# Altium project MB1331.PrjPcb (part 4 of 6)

## Sheet MFX.SchDoc: MFX I/O Expander
size A4; Date: Not used; ApprovedBy: Not used; CheckedBy: Not used; Author: Not used; CompanyName: STMicroelectronics; DrawnBy: Not used; Engineer: Not used; Organization: Not used; Address1: Not used; Address2: Not used; Address3: Not used; Address4: Not used; DocumentNumber: Not used; Revision: Not used; SheetNumber: 18; SheetTotal: 23
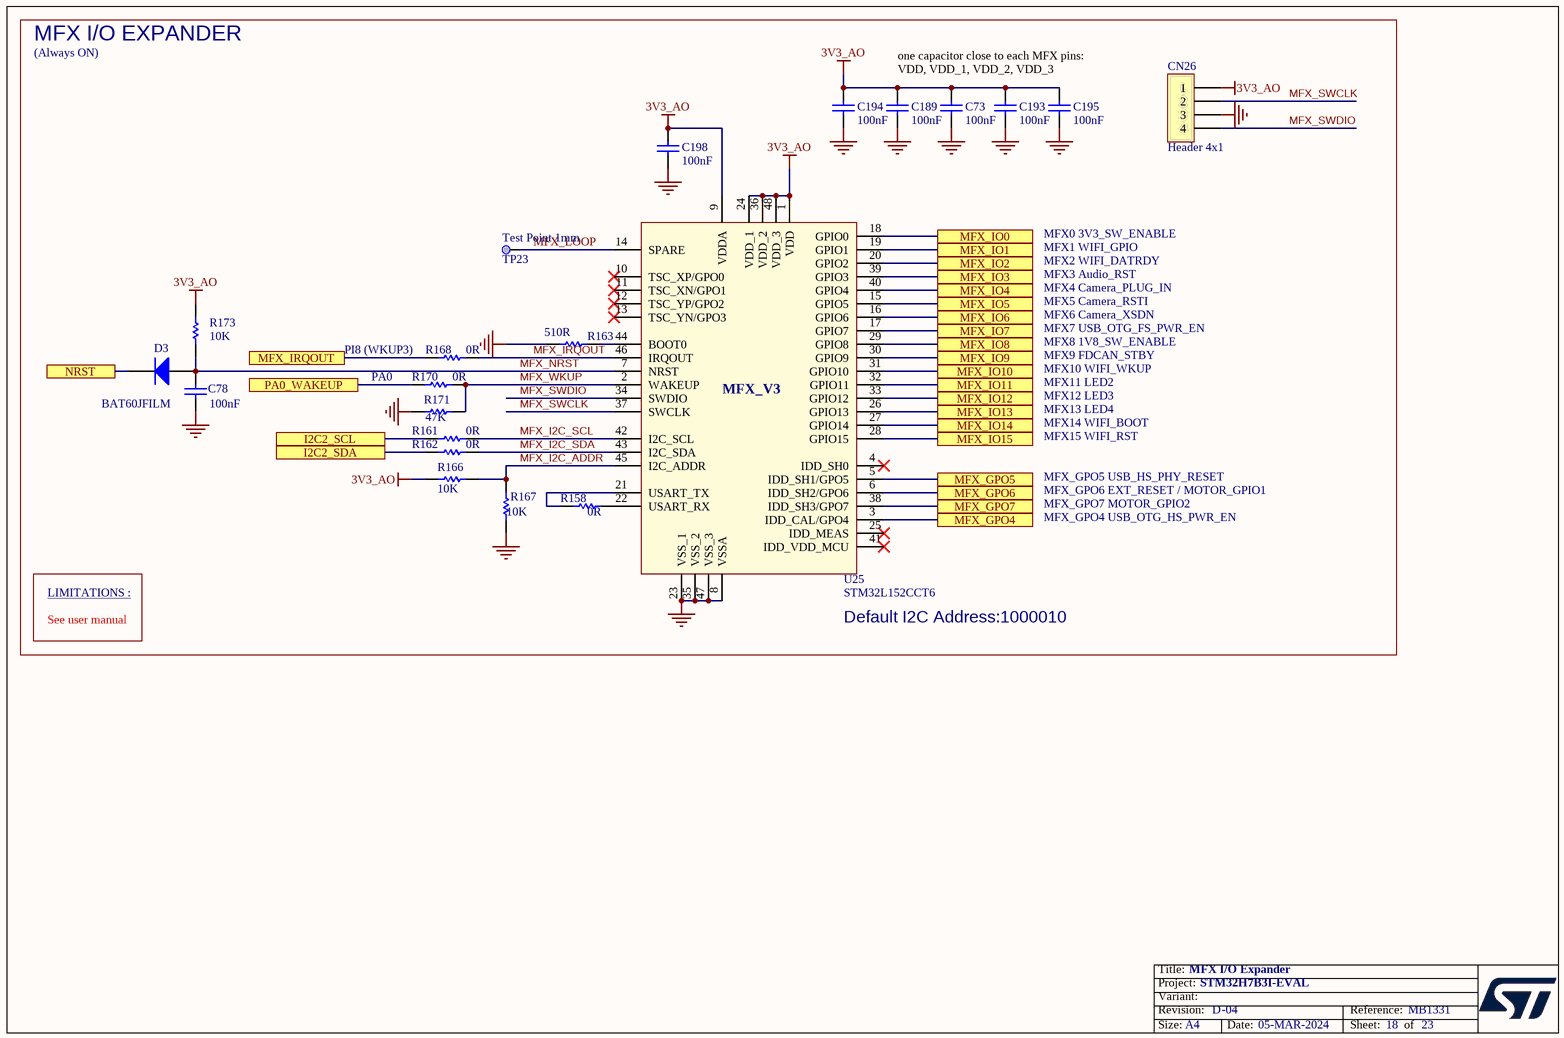
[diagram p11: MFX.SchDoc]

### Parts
C73  value 100nF  [C0402]  (hidden comment: Capacitor)
C78  value 100nF  [C0402]  (hidden comment: Capacitor)
C189  value 100nF  [C0402]  (hidden comment: Capacitor)
C193  value 100nF  [C0402]  (hidden comment: Capacitor)
C194  value 100nF  [C0402]  (hidden comment: Capacitor)
C195  value 100nF  [C0402]  (hidden comment: Capacitor)
C198  value 100nF  [C0402]  (hidden comment: Capacitor)
CN26  Header 4x1  [CON_SAMTEC_TSW-104-07-G-S]
D3  BAT60JFILM  [DIO_SOD323]
R158  value 0R  [R0603]  (hidden comment: Resistor)
R161  value 0R  [R0402]  (hidden comment: Resistor)
R162  value 0R  [R0402]  (hidden comment: Resistor)
R163  value 510R  [R0402]  (hidden comment: Resistor)
R166  value 10K  [R0402]  (hidden comment: Resistor)
R167  value 10K  [R0402]  (hidden comment: Resistor)
R168  value 0R  [R0603]  (hidden comment: Resistor)
R170  value 0R  [R0603]  (hidden comment: Resistor)
R171  value 47K  [R0402]  (hidden comment: Resistor)
R173  value 10K  [R0402]  (hidden comment: Resistor)
TP23  value Test Point 1mm  [TP_SMD_1MM]  (hidden comment: Test Point)  (no BOM)
U25  STM32L152CCT6  [ICC_LQFP48_7X7_P050]

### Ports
I2C2_SCL, I2C2_SDA, MFX_GPO4, MFX_GPO5, MFX_GPO6, MFX_GPO7, MFX_IO0, MFX_IO1, MFX_IO2, MFX_IO3, MFX_IO4, MFX_IO5, MFX_IO6, MFX_IO7, MFX_IO8, MFX_IO9, MFX_IO10, MFX_IO11, MFX_IO12, MFX_IO13, MFX_IO14, MFX_IO15, MFX_IRQOUT, NRST, PA0_WAKEUP

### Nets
3V3_AO: C73.1 C189.2 C193.2 C194.2 C195.2 C198.2 CN26.1 R166.1 R173.2 U25.1(VDD) U25.9(VDDA) U25.24(VDD_1) U25.36(VDD_2) U25.48(VDD_3)
GND: C73.2 C78.1 C189.1 C193.1 C194.1 C195.1 C198.1 CN26.3 R163.2 R167.2 R171.1 U25.8(VSSA) U25.23(VSS_1) U25.35(VSS_2) U25.47(VSS_3)
I2C2_SCL: R161.1 ; port I2C2_SCL
I2C2_SDA: R162.1 ; port I2C2_SDA
MFX_GPO4: U25.3(IDD_CAL/GPO4) ; port MFX_GPO4
MFX_GPO5: U25.5(IDD_SH1/GPO5) ; port MFX_GPO5
MFX_GPO6: U25.6(IDD_SH2/GPO6) ; port MFX_GPO6
MFX_GPO7: U25.38(IDD_SH3/GPO7) ; port MFX_GPO7
MFX_I2C_ADDR: R166.2 R167.1 U25.45(I2C_ADDR)
MFX_I2C_SCL: R161.2 U25.42(I2C_SCL)
MFX_I2C_SDA: R162.2 U25.43(I2C_SDA)
MFX_IO0: U25.18(GPIO0) ; port MFX_IO0
MFX_IO1: U25.19(GPIO1) ; port MFX_IO1
MFX_IO2: U25.20(GPIO2) ; port MFX_IO2
MFX_IO3: U25.39(GPIO3) ; port MFX_IO3
MFX_IO4: U25.40(GPIO4) ; port MFX_IO4
MFX_IO5: U25.15(GPIO5) ; port MFX_IO5
MFX_IO6: U25.16(GPIO6) ; port MFX_IO6
MFX_IO7: U25.17(GPIO7) ; port MFX_IO7
MFX_IO8: U25.29(GPIO8) ; port MFX_IO8
MFX_IO9: U25.30(GPIO9) ; port MFX_IO9
MFX_IO10: U25.31(GPIO10) ; port MFX_IO10
MFX_IO11: U25.32(GPIO11) ; port MFX_IO11
MFX_IO12: U25.33(GPIO12) ; port MFX_IO12
MFX_IO13: U25.26(GPIO13) ; port MFX_IO13
MFX_IO14: U25.27(GPIO14) ; port MFX_IO14
MFX_IO15: U25.28(GPIO15) ; port MFX_IO15
MFX_IRQOUT: R168.2 U25.46(IRQOUT)
MFX_LOOP: TP23.1 U25.14(SPARE)
MFX_NRST: C78.2 D3.1(A) R173.1 U25.7(NRST)
MFX_SWCLK: CN26.2 U25.37(SWCLK)
MFX_SWDIO: CN26.4 U25.34(SWDIO)
MFX_WKUP: R170.1 R171.2 U25.2(WAKEUP)
NRST: D3.2(K) ; port NRST
PA0_WAKEUP: R170.2 ; port PA0_WAKEUP
PI8: R168.1 ; port MFX_IRQOUT
NetR158_1: R158.1 U25.21(USART_TX)
NetR158_2: R158.2 U25.22(USART_RX)
NetR163_1: R163.1 U25.44(BOOT0)

Not connected (* = marked no-connect by the designer): U25 4(IDD_SH0)* 10(TSC_XP/GPO0)* 11(TSC_XN/GPO1)* 12(TSC_YP/GPO2)* 13(TSC_YN/GPO3)* 25(IDD_MEAS)* 41(IDD_VDD_MCU)*

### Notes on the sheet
- MFX I/O EXPANDER
- (Always ON)
- one capacitor close to each MFX pins: VDD, VDD_1, VDD_2, VDD_3
- PI8 (WKUP3)
- PA0
- MFX0	3V3_SW_ENABLE
  MFX1	WIFI_GPIO
  MFX2	WIFI_DATRDY
  MFX3	Audio_RST
  MFX4	Camera_PLUG_IN
  MFX5	Camera_RSTI
  MFX6	Camera_XSDN
  MFX7	USB_OTG_FS_PWR_EN
  MFX8	1V8_SW_ENABLE
  MFX9	FDCAN_STBY
  MFX10	WIFI_WKUP
  MFX11	LED2
  MFX12	LED3
  MFX13	LED4
  MFX14	WIFI_BOOT
  MFX15	WIFI_RST
- MFX_GPO5	USB_HS_PHY_RESET
  MFX_GPO6	EXT_RESET / MOTOR_GPIO1
  MFX_GPO7	MOTOR_GPIO2
  MFX_GPO4	USB_OTG_HS_PWR_EN
- LIMITATIONS :
- See user manual
- (near U25) Default I2C Address:1000010

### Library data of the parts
C73 C78 C189 C193-C195 C198 = MCD-00006: Capacitor, MLCC, 100nF, 16V, X7R, 10%, 0402, T=0.5mm; Manufacturer_Part_Number: CC0402KRX7R7BB104; Manufacturer: YAGEO; Alternate_Manufacturer_Part_Number: GCM155R71C104KA55D; Alternate_Manufacturer: MURATA; Part_Preference: Recommended; Partial_Alternate_Internal_Part_Number: MCD-03299; Provided_By: SUBCO; ECCN_US: EAR99; ECCN_EU: NEC; Component_Country_Of_Origin: China; ID: 2474; Order_Code_RS: 9402047; ShowFields: YES
CN26 = MCD-00029: Header, 4x1, 2,54mm, VR, TH, Height 5.84mm/2.54mm; Manufacturer_Part_Number: TSW-104-07-G-S; Manufacturer: SAMTEC; Part_Type: Connector; Part_Preference: Recommended; Provided_By: SUBCO; Component_Country_Of_Origin: China, Costa Rica, Malaysia, USA, Vietnam; ID: 2487; Order_Code_RS: 2667450; ShowFields: YES
D3 = MCD-00034: Manufacturer: STMICROELECTRONICS; Part_Type: Diode; BMS_Part_Number: 9151097; Manufacturer_HQ_COO: EU; Part_Preference: Recommended; Provided_By: SUBCO with ST control; ECCN_US: EAR99; ECCN_EU: NEC; Component_Country_Of_Origin: China; ID: 2483; Order_Code_RS: 714-6879; ShowFields: YES
R158 R168 R170 = MCD-00056: Resistor,0R,0603,5%,1/10W; Manufacturer_Part_Number: RC0603JR-070RL; Manufacturer: YAGEO; Part_Preference: Recommended; Provided_By: SUBCO; ECCN_US: EAR99; ECCN_EU: NEC; Component_Country_Of_Origin: China; ID: 2536; Order_Code_RS: 9233130RL; ShowFields: YES
R161 R162 = MCD-00052: Resistor,0R,0402,5%,1/16W; Manufacturer_Part_Number: RC0402JR-070RL; Manufacturer: YAGEO; Part_Preference: Recommended; Provided_By: SUBCO; ECCN_US: EAR99; ECCN_EU: NEC; Component_Country_Of_Origin: China; ID: 2540; Order_Code_RS: 9232516RL; ShowFields: YES
R163 = MCD-00064: Resistor,510R,0402,1%,1/16W; Manufacturer_Part_Number: RC0402FR-07510RL; Manufacturer: YAGEO; Part_Preference: Recommended; Provided_By: SUBCO; ECCN_US: EAR99; ECCN_EU: NEC; Component_Country_Of_Origin: China; ID: 2525; Order_Code_RS: 1458804; ShowFields: YES
R166 R167 R173 = MCD-00053: Resistor,10K,0402,1%,1/16W; Manufacturer_Part_Number: RC0402FR-0710KL; Manufacturer: YAGEO; BMS_Part_Number: 9131590; Part_Preference: Recommended; Provided_By: SUBCO; ECCN_US: EAR99; ECCN_EU: NEC; Component_Country_Of_Origin: China; ID: 2539; Order_Code_RS: 9239359; ShowFields: YES
R171 = MCD-00063: Resistor,47K,0402,1%,1/16W; Manufacturer_Part_Number: RC0402FR-0747KL; Manufacturer: YAGEO; Part_Preference: Recommended; Provided_By: SUBCO; ECCN_US: EAR99; ECCN_EU: NEC; Component_Country_Of_Origin: China; ID: 2528; Order_Code_RS: 9239430; ShowFields: YES
TP23 = MCD-00074: Test Point 1mm; Part_Type: Misc; Part_Preference: Recommended; Component_Country_Of_Origin: Unknown; ID: 2518; ShowFields: YES
U25 = MCD-00135: Ultra-low-power 32-bit MCU ARM; Manufacturer: STMICROELECTRONICS; Part_Type: IC; BMS_Part_Number: 9175875; Manufacturer_HQ_COO: EU; Part_Preference: Forbidden; Provided_By: SUBCO with ST control; ECCN_US: 3A991A2; ECCN_EU: NEC; Component_Country_Of_Origin: China; ID: 2734; Order_Code_RS: 110-7090; ShowFields: YES

## Sheet MotorControl.SchDoc: Motor Control
size A4; SheetNumber: 17; SheetTotal: 23
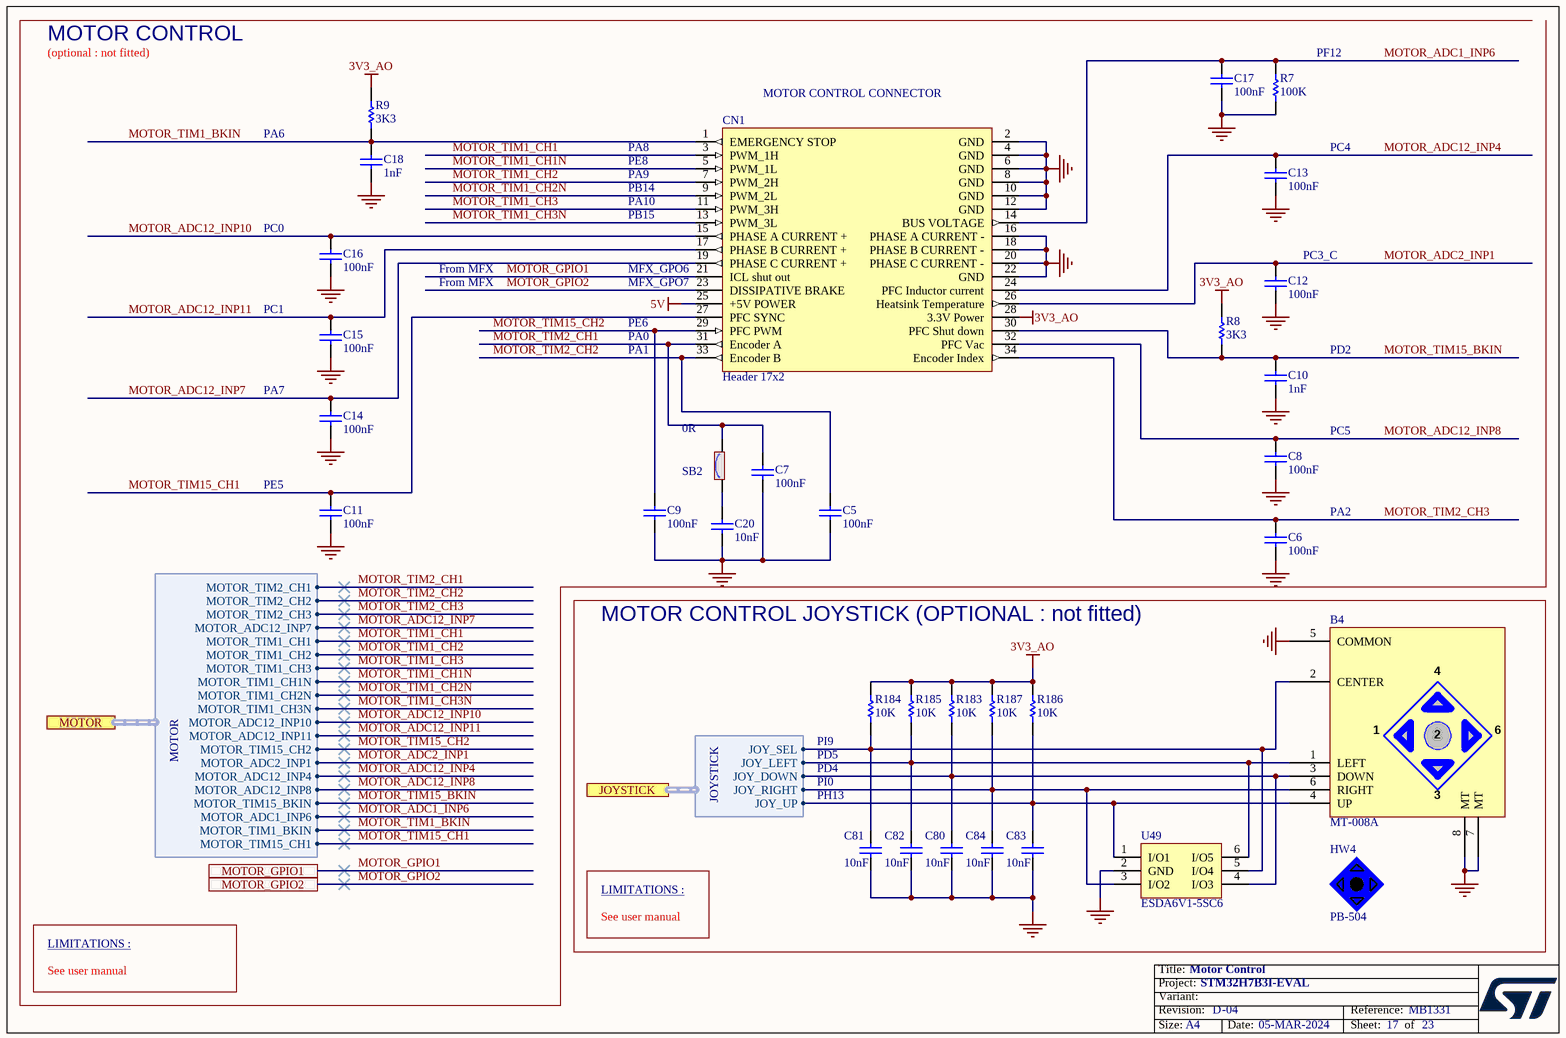
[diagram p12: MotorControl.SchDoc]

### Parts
B4  value MT-008A  [SWI_XIEJIA_MT-008A_6P]  (hidden comment: Joystick MT-008A_M)
C5  value 100nF  [C0402]  (hidden comment: Capacitor)
C6  value 100nF  [C0402]  (hidden comment: Capacitor)
C7  value 100nF  [C0402]  (hidden comment: Capacitor)
C8  value 100nF  [C0402]  (hidden comment: Capacitor)
C9  value 100nF  [C0402]  (hidden comment: Capacitor)
C10  value 1nF  [C0402]  (hidden comment: Capacitor)
C11  value 100nF  [C0402]  (hidden comment: Capacitor)
C12  value 100nF  [C0402]  (hidden comment: Capacitor)
C13  value 100nF  [C0402]  (hidden comment: Capacitor)
C14  value 100nF  [C0402]  (hidden comment: Capacitor)
C15  value 100nF  [C0402]  (hidden comment: Capacitor)
C16  value 100nF  [C0402]  (hidden comment: Capacitor)
C17  value 100nF  [C0402]  (hidden comment: Capacitor)
C18  value 1nF  [C0402]  (hidden comment: Capacitor)
C20  value 10nF  [C0402]  (hidden comment: Capacitor)
C80  value 10nF  [C0402]  (hidden comment: Capacitor)
C81  value 10nF  [C0402]  (hidden comment: Capacitor)
C82  value 10nF  [C0402]  (hidden comment: Capacitor)
C83  value 10nF  [C0402]  (hidden comment: Capacitor)
C84  value 10nF  [C0402]  (hidden comment: Capacitor)
CN1  value Header 17x2  [CON_SAMTEC_TST-117-01-T-D]  (hidden comment: Header 17x2 IDC34 MotorControl)
HW4  value PB-504  (hidden comment: JOYSTICK_BLUE_HAT)  (mechanical)
R7  value 100K  [R0603]  (hidden comment: Resistor)
R8  value 3K3  [R0402]  (hidden comment: Resistor)
R9  value 3K3  [R0402]  (hidden comment: Resistor)
R183  value 10K  [R0402]  (hidden comment: Resistor)
R184  value 10K  [R0402]  (hidden comment: Resistor)
R185  value 10K  [R0402]  (hidden comment: Resistor)
R186  value 10K  [R0402]  (hidden comment: Resistor)
R187  value 10K  [R0402]  (hidden comment: Resistor)
SB2  value 0R  [SOLDER-BRIDGE_R0603-0R]  (hidden comment: SB_ON)
U49  ESDA6V1-5SC6  [ESD_SOT23-6L]

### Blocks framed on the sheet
MOTOR CONTROL JOYSTICK (OPTIONAL : not fitted): B4 C80-C84 HW4 R183-R187 U49

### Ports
JOYSTICK (harness JOYSTICK), MOTOR (harness MOTOR), MOTOR_GPIO1, MOTOR_GPIO2

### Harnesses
MOTOR: MOTOR_TIM2_CH1, MOTOR_TIM2_CH2, MOTOR_TIM2_CH3, MOTOR_ADC12_INP7, MOTOR_TIM1_CH1, MOTOR_TIM1_CH2, MOTOR_TIM1_CH3, MOTOR_TIM1_CH1N, MOTOR_TIM1_CH2N, MOTOR_TIM1_CH3N, MOTOR_ADC12_INP10, MOTOR_ADC12_INP11, MOTOR_TIM15_CH2, MOTOR_ADC2_INP1, MOTOR_ADC12_INP4, MOTOR_ADC12_INP8, MOTOR_TIM15_BKIN, MOTOR_ADC1_INP6, MOTOR_TIM1_BKIN, MOTOR_TIM15_CH1
JOYSTICK: JOY_SEL, JOY_LEFT, JOY_DOWN, JOY_RIGHT, JOY_UP

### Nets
3V3_AO: CN1.28(3.3V_Power) R8.2 R9.2 R183.2 R184.2 R185.2 R186.2 R187.2
5V: CN1.25(+5V_POWER)
GND: B4.5(COMMON) B4.7(MT) B4.8(MT) C5.1 C6.1 C7.1 C8.1 C9.1 C10.1 C11.1 C12.1 C13.1 C14.1 C15.1 C16.1 C17.1 C18.1 C20.1 C80.1 C81.1 C82.1 C83.1 C84.1 CN1.2(GND) CN1.4(GND) CN1.6(GND) CN1.8(GND) CN1.10(GND) CN1.12(GND) CN1.16(PHASE_A_CURRENT_-) CN1.18(PHASE_B_CURRENT_-) CN1.20(PHASE_C_CURRENT_-) CN1.22(GND) R7.1 U49.2(GND)
MOTOR_ADC1_INP6: C17.2 CN1.14(BUS_VOLTAGE) R7.2 ; port MOTOR.MOTOR_ADC1_INP6
MOTOR_ADC2_INP1: C12.2 CN1.26(Heatsink_Temperature) ; port MOTOR.MOTOR_ADC2_INP1
MOTOR_ADC12_INP4: C13.2 CN1.24(PFC_Inductor_current) ; port MOTOR.MOTOR_ADC12_INP4
MOTOR_ADC12_INP7: C14.2 CN1.19(PHASE_C_CURRENT_+) ; port MOTOR.MOTOR_ADC12_INP7
MOTOR_ADC12_INP8: C8.2 CN1.32(PFC_Vac) ; port MOTOR.MOTOR_ADC12_INP8
MOTOR_ADC12_INP10: C16.2 CN1.15(PHASE_A_CURRENT_+) ; port MOTOR.MOTOR_ADC12_INP10
MOTOR_ADC12_INP11: C15.2 CN1.17(PHASE_B_CURRENT_+) ; port MOTOR.MOTOR_ADC12_INP11
MOTOR_GPIO1: CN1.21(ICL_shut_out) ; port MOTOR_GPIO1
MOTOR_GPIO2: CN1.23(DISSIPATIVE_BRAKE) ; port MOTOR_GPIO2
MOTOR_TIM1_BKIN: C18.2 CN1.1(EMERGENCY_STOP) R9.1 ; port MOTOR.MOTOR_TIM1_BKIN
MOTOR_TIM1_CH1: CN1.3(PWM_1H) ; port MOTOR.MOTOR_TIM1_CH1
MOTOR_TIM1_CH1N: CN1.5(PWM_1L) ; port MOTOR.MOTOR_TIM1_CH1N
MOTOR_TIM1_CH2: CN1.7(PWM_2H) ; port MOTOR.MOTOR_TIM1_CH2
MOTOR_TIM1_CH2N: CN1.9(PWM_2L) ; port MOTOR.MOTOR_TIM1_CH2N
MOTOR_TIM1_CH3: CN1.11(PWM_3H) ; port MOTOR.MOTOR_TIM1_CH3
MOTOR_TIM1_CH3N: CN1.13(PWM_3L) ; port MOTOR.MOTOR_TIM1_CH3N
MOTOR_TIM2_CH1: C7.2 CN1.31(Encoder_A) SB2.1 ; port MOTOR.MOTOR_TIM2_CH1
MOTOR_TIM2_CH2: C5.2 CN1.33(Encoder_B) ; port MOTOR.MOTOR_TIM2_CH2
MOTOR_TIM2_CH3: C6.2 CN1.34(Encoder_Index) ; port MOTOR.MOTOR_TIM2_CH3
MOTOR_TIM15_BKIN: C10.2 CN1.30(PFC_Shut_down) R8.1 ; port MOTOR.MOTOR_TIM15_BKIN
MOTOR_TIM15_CH1: C11.2 CN1.27(PFC_SYNC) ; port MOTOR.MOTOR_TIM15_CH1
MOTOR_TIM15_CH2: C9.2 CN1.29(PFC_PWM) ; port MOTOR.MOTOR_TIM15_CH2
NetB4_1: B4.1(LEFT) C82.2 R185.1 U49.6(I/O5) ; port JOYSTICK.JOY_LEFT
NetB4_2: B4.2(CENTER) C81.2 R184.1 U49.5(I/O4) ; port JOYSTICK.JOY_SEL
NetB4_3: B4.3(DOWN) C80.2 R183.1 U49.4(I/O3) ; port JOYSTICK.JOY_DOWN
NetB4_4: B4.4(UP) C83.2 R186.1 U49.1(I/O1) ; port JOYSTICK.JOY_UP
NetB4_6: B4.6(RIGHT) C84.2 R187.1 U49.3(I/O2) ; port JOYSTICK.JOY_RIGHT
NetC20_2: C20.2 SB2.2

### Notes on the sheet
- MOTOR CONTROL
- (optional : not fitted)
- (near CN1) MOTOR CONTROL CONNECTOR
- (near R7) PF12
- PA6
- PA9
- PA8
- PE8
- PC4
- (near C16) PC0
- PB14
- PB15
- PA10
- PC1
- From MFX
- (near CN1) MFX_GPO6
- (near CN1) MFX_GPO7
- (near C12) PC3_C
- PA1
- PA0
- PE6
- PD2
- PA7
- PC5
- PE5
- PA2
- (near R184) PD5
- PD4
- PI0
- (near R184) PI9
- PH13
- LIMITATIONS :
- See user manual

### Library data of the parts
B4 = MCD-00132: Joystick, 4 dir, 1 OK; Part_Type: Misc; Manufacturer: XIEJIA Electronics; BMS_Part_Number: 9180124; Part_Preference: Recommended; Provided_By: SUBCO; Component_Country_Of_Origin: Unknown; ID: 2736; ShowFields: YES
C5-C9 C11-C17 = MCD-00006: as C73 on sheet MFX
C10 C18 = MCD-00198: Capacitor, MLCC, 1nF, 16V, X7R, 10%, 0402, T=0.5mm; Manufacturer_Part_Number: CC0402KRX7R7BB102; Manufacturer: YAGEO; Part_Preference: Recommended; Provided_By: SUBCO; ECCN_US: EAR99; ECCN_EU: NEC; Component_Country_Of_Origin: China; ID: 2665; ShowFields: YES
C20 C80-C84 = MCD-00011: Capacitor, MLCC, 10nF, 16V, X7R, 10%, 0402, T=0.5mm; Manufacturer_Part_Number: CC0402KRX7R7BB103; Manufacturer: YAGEO; Part_Preference: Recommended; Provided_By: SUBCO; ECCN_US: EAR99; ECCN_EU: NEC; Component_Country_Of_Origin: China; ID: 2469; Order_Code_RS: 3019275; ShowFields: YES
CN1 = MCD-00583: Header, 17x2, 2.54mm, VR, TH, Height 8.89mm/2.92mm, shrouded; Manufacturer_Part_Number: TST-117-01-T-D; Manufacturer: SAMTEC; Part_Type: Connector; Alternate_Manufacturer_Part_Number: BHFS03-34G01BT1; Alternate_Manufacturer: WINPIN; Part_Preference: Recommended; Provided_By: SUBCO; Component_Country_Of_Origin: China, Costa Rica, Malaysia, USA, Vietnam; ID: 3161; ShowFields: YES
HW4 = MCD-01337: Joystick Blue Hat; Part_Type: Misc; Manufacturer: JIUBABA; Part_Preference: Alternate; Provided_By: SUBCO; Alternate_EMS: A; Component_Country_Of_Origin: Unknown; ID: 3437; ShowFields: YES
R7 = MCD-00223: Resistor,100K,0603,1%,1/10W; Manufacturer_Part_Number: RC0603FR-07100KL; Manufacturer: YAGEO; Part_Preference: Recommended; Provided_By: SUBCO; ECCN_US: EAR99; ECCN_EU: NEC; Component_Country_Of_Origin: China; ID: 2647; ShowFields: YES
R8 R9 = MCD-00184: Resistor,3K3,0402,1%,1/16W; Manufacturer_Part_Number: RC0402FR-073K3L; Manufacturer: YAGEO; BMS_Part_Number: 9131946; Part_Preference: Recommended; Provided_By: SUBCO; ECCN_US: EAR99; ECCN_EU: NEC; Component_Country_Of_Origin: China; ID: 2684; ShowFields: YES
R183-R187 = MCD-00053: as R166 on sheet MFX
SB2 = MCD-00071: Solder Bridge ON; Part_Type: Resistor; Manufacturer_Part_Number: RC0603JR-070RL; Manufacturer: YAGEO; Manufacturer_HQ_COO: Unknown; Part_Preference: Recommended; Provided_By: SUBCO; Component_Country_Of_Origin: China; ID: 2521; Order_Code_RS: 199-5647; ShowFields: YES
U49 = MCD-01066: 5 unidirectional Transil diodes ESD protection; Part_Type: Diode; Manufacturer: STMICROELECTRONICS; BMS_Part_Number: 9179044; Manufacturer_HQ_COO: EU; Part_Preference: Recommended; Provided_By: SUBCO with ST control; ECCN_US: EAR99; ECCN_EU: NEC; Component_Country_Of_Origin: China; ID: 3425; Order_Code_RS: 250-066; ShowFields: YES

## Sheet OCSPI.SchDoc: OCSPI
size A4; Date: Not used; ApprovedBy: Not used; CheckedBy: Not used; Author: Not used; CompanyName: STMicroelectronics; DrawnBy: Not used; Engineer: Not used; Organization: Not used; Address1: Not used; Address2: Not used; Address3: Not used; Address4: Not used; DocumentNumber: Not used; Revision: Not used; SheetNumber: 8; SheetTotal: 23
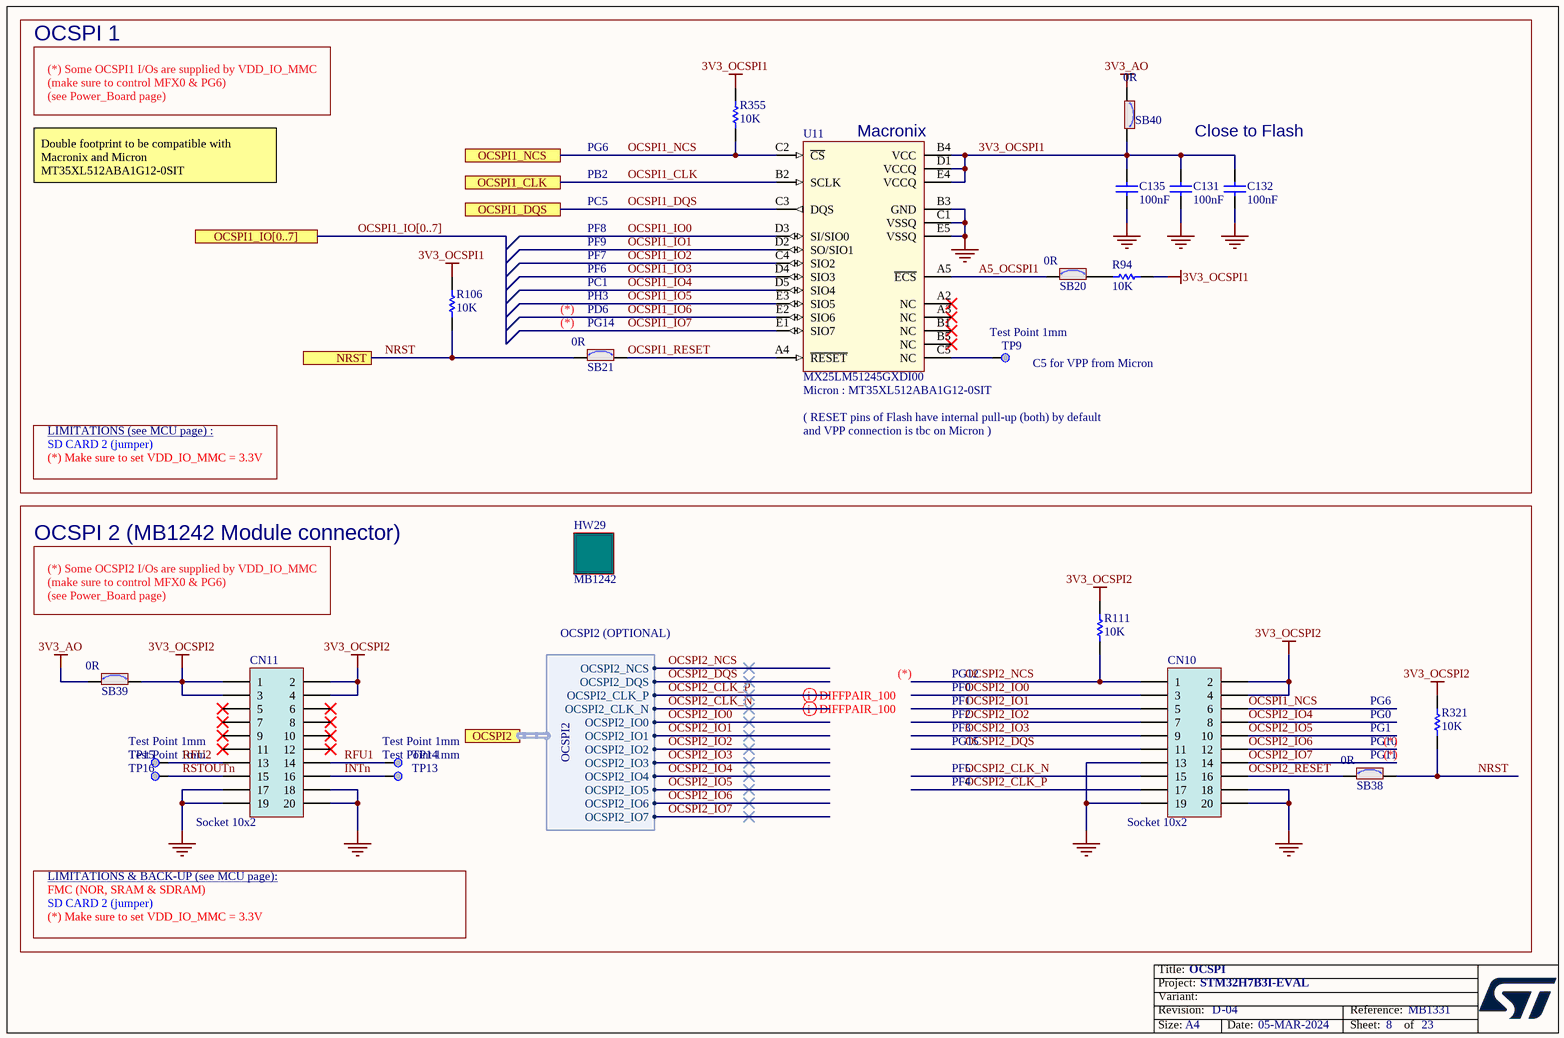
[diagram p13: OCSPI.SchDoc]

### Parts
C131  value 100nF  [C0402]  (hidden comment: Capacitor)
C132  value 100nF  [C0402]  (hidden comment: Capacitor)
C135  value 100nF  [C0402]  (hidden comment: Capacitor)
CN10  Socket 10x2  [CON_SAMTEC_ERF8-010-050-S-DV-TR]
CN11  Socket 10x2  [CON_SAMTEC_ERF8-010-050-S-DV-TR]
HW29  value MB1242  [MOD_ERM8_BGA24-OCTAL-SPI_MB1242]  (hidden comment: Daughter_Board)
R94  value 10K  [R0402]  (hidden comment: Resistor)
R106  value 10K  [R0402]  (hidden comment: Resistor)
R111  value 10K  [R0402]  (hidden comment: Resistor)
R321  value 10K  [R0402]  (hidden comment: Resistor)
R355  value 10K  [R0402]  (hidden comment: Resistor)
SB20  value 0R  [SOLDER-BRIDGE_R0603-0R]  (hidden comment: SB_ON)
SB21  value 0R  [SOLDER-BRIDGE_R0603-0R]  (hidden comment: SB_ON)
SB38  value 0R  [SOLDER-BRIDGE_R0603-0R]  (hidden comment: SB_ON)
SB39  value 0R  [SOLDER-BRIDGE_R0603-0R]  (hidden comment: SB_ON)
SB40  value 0R  [SOLDER-BRIDGE_R0603-0R]  (hidden comment: SB_ON)
TP9  value Test Point 1mm  [TP_SMD_1MM]  (hidden comment: Test Point)  (no BOM)
TP13  value Test Point 1mm  [TP_SMD_1MM]  (hidden comment: Test Point)  (no BOM)
TP14  value Test Point 1mm  [TP_SMD_1MM]  (hidden comment: Test Point)  (no BOM)
TP15  value Test Point 1mm  [TP_SMD_1MM]  (hidden comment: Test Point)  (no BOM)
TP16  value Test Point 1mm  [TP_SMD_1MM]  (hidden comment: Test Point)  (no BOM)
U11  MX25LM51245GXDI00  [ICC_BGA24_5X5-BALL-ARRAY_6X8_P1]

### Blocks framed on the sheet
OCSPI 1: C131 C132 C135 R94 R106 R355 SB20 SB21 SB40 TP9 U11
OCSPI 2 (MB1242 Module connector): CN10 CN11 HW29 R111 R321 SB38 SB39 TP13-TP16

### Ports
NRST, OCSPI1_CLK, OCSPI1_DQS, OCSPI1_IO[0..7], OCSPI1_NCS, OCSPI2 (harness OCSPI2)

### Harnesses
OCSPI2: OCSPI2_NCS, OCSPI2_DQS, OCSPI2_CLK_P, OCSPI2_CLK_N, OCSPI2_IO0, OCSPI2_IO1, OCSPI2_IO2, OCSPI2_IO3, OCSPI2_IO4, OCSPI2_IO5, OCSPI2_IO6, OCSPI2_IO7

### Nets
3V3_AO: SB39.2 SB40.1
3V3_OCSPI1: C131.2 C132.2 C135.2 R94.2 R106.1 R355.1 SB40.2 U11.B4(VCC) U11.D1(VCCQ) U11.E4(VCCQ)
3V3_OCSPI2: CN10.2 CN10.4 CN11.1 CN11.2 CN11.3 CN11.4 R111.1 R321.1 SB39.1
GND: C131.1 C132.1 C135.1 CN10.13 CN10.18 CN10.19 CN10.20 CN11.17 CN11.18 CN11.19 CN11.20 U11.B3(GND) U11.C1(VSSQ) U11.E5(VSSQ)
A5_OCSPI1: SB20.1 U11.A5(~{ECS})
INTn: CN11.16 TP13.1
NRST: R106.2 R321.2 SB21.1 SB38.1 ; port NRST
OCSPI1_CLK: U11.B2(SCLK) ; port OCSPI1_CLK
OCSPI1_DQS: U11.C3(DQS) ; port OCSPI1_DQS
OCSPI1_IO0: U11.D3(SI/SIO0)
OCSPI1_IO1: U11.D2(SO/SIO1)
OCSPI1_IO2: U11.C4(SIO2)
OCSPI1_IO3: U11.D4(SIO3)
OCSPI1_IO4: U11.D5(SIO4)
OCSPI1_IO5: U11.E3(SIO5)
OCSPI1_IO6: U11.E2(SIO6)
OCSPI1_IO7: U11.E1(SIO7)
OCSPI1_NCS: CN10.6 R355.2 U11.C2(~{CS}) ; port OCSPI1_NCS
OCSPI1_RESET: SB21.2 U11.A4(~{RESET})
OCSPI2_CLK_N: CN10.15 ; port OCSPI2.OCSPI2_CLK_N
OCSPI2_CLK_P: CN10.17 ; port OCSPI2.OCSPI2_CLK_P
OCSPI2_DQS: CN10.11 ; port OCSPI2.OCSPI2_DQS
OCSPI2_IO0: CN10.3 ; port OCSPI2.OCSPI2_IO0
OCSPI2_IO1: CN10.5 ; port OCSPI2.OCSPI2_IO1
OCSPI2_IO2: CN10.7 ; port OCSPI2.OCSPI2_IO2
OCSPI2_IO3: CN10.9 ; port OCSPI2.OCSPI2_IO3
OCSPI2_IO4: CN10.8 ; port OCSPI2.OCSPI2_IO4
OCSPI2_IO5: CN10.10 ; port OCSPI2.OCSPI2_IO5
OCSPI2_IO6: CN10.12 ; port OCSPI2.OCSPI2_IO6
OCSPI2_IO7: CN10.14 ; port OCSPI2.OCSPI2_IO7
OCSPI2_NCS: CN10.1 R111.2 ; port OCSPI2.OCSPI2_NCS
OCSPI2_RESET: CN10.16 SB38.2
RFU1: CN11.14 TP14.1
RFU2: CN11.13 TP15.1
RSTOUTn: CN11.15 TP16.1
NetR94_1: R94.1 SB20.2
NetTP9_1: TP9.1 U11.C5(NC)

Not connected (* = marked no-connect by the designer): CN11 5* 6* 7* 8* 9* 10* 11* 12*; U11 A2(NC)* A3(NC)* B1(NC)* B5(NC)*

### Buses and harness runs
bus OCSPI1_IO[0..7] = port OCSPI1_IO[0..7]

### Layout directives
differential pair: OCSPI2_CLK_N, OCSPI2_CLK_P

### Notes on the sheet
- (*) Some OCSPI1 I/Os are supplied by VDD_IO_MMC
  (make sure to control MFX0 & PG6)
  (see Power_Board page)
- Double footprint to be compatible with Macronix and Micron MT35XL512ABA1G12-0SIT
- PB2
- PG6
- (near U11) Macronix
- Close to Flash
- PF8
- PC5
- PF9
- (near SB21) (*)
- PF6
- PH3
- PC1
- (near SB21) PD6
- PF7
- (near SB21) PG14
- (near TP9) C5 for VPP from Micron
- LIMITATIONS (see MCU page) :
- SD CARD 2 (jumper)
- ( RESET pins of Flash have internal pull-up (both) by default
- and VPP connection is tbc on Micron )
- Micron : MT35XL512ABA1G12-0SIT
- (*) Make sure to set VDD_IO_MMC = 3.3V
- (*) Some OCSPI2 I/Os are supplied by VDD_IO_MMC
  (make sure to control MFX0 & PG6)
  (see Power_Board page)
- OCSPI2 (OPTIONAL)
- (*)
- PF0
- PF2
- PF1
- PG12
- PG0
- PF3
- PF4
- PF5
- PG15
- (near SB38) PG1
- (near SB38) PG10
- (near SB38) PG11
- (near SB38) (*)
- LIMITATIONS & BACK-UP (see MCU page):
- FMC (NOR, SRAM & SDRAM)

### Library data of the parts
C131 C132 C135 = MCD-00006: as C73 on sheet MFX
CN10 CN11 = MCD-00675: Socket High Speed, 10x2, 0.8mm, Center Strip Contacts, VR, SMT, Height 5.33 mm; Part_Type: Connector; Manufacturer_Part_Number: ERF8-010-05.0-S-DV-TR; Manufacturer: SAMTEC; Part_Preference: Recommended; Provided_By: SUBCO; ECCN_US: EAR99; ECCN_EU: NEC; Component_Country_Of_Origin: China, Costa Rica, Malaysia, USA, Vietnam; ID: 3071; Order_Code_RS: 766-8868; ShowFields: YES
HW29 = MCD-01033: MB1242 - ERM8 BGA24 Octal SPI module; Part_Type: Misc; Manufacturer: STMICROELECTRONICS; Part_Preference: Recommended; Provided_By: SUBCO with ST control; Component_Country_Of_Origin: Unknown; ID: 2990; ShowFields: YES
R94 R106 R111 R321 R355 = MCD-00053: as R166 on sheet MFX
SB20 SB21 SB38-SB40 = MCD-00071: as SB2 on sheet MotorControl
TP9 TP13-TP16 = MCD-00074: as TP23 on sheet MFX
U11 = MCD-00246: Memory,Octo-SPI-NOR,512Mb,2048x16,133MHz,3V,DTR,BGA24, CMOS MXSMIO; Part_Type: IC; Manufacturer: MACRONIX; Part_Preference: Recommended; Provided_By: SUBCO; ECCN_US: 3A991.b.1.a; Component_Country_Of_Origin: Taiwan°; ID: 2623; ShowFields: YES

## Sheet Peripherals.SchDoc: Peripherals
size A4; Date: Not used; ApprovedBy: Not used; CheckedBy: Not used; Author: Not used; CompanyName: STMicroelectronics; DrawnBy: Not used; Engineer: Not used; Organization: Not used; Address1: Not used; Address2: Not used; Address3: Not used; Address4: Not used; DocumentNumber: Not used; Revision: Not used; SheetNumber: 14; SheetTotal: 23
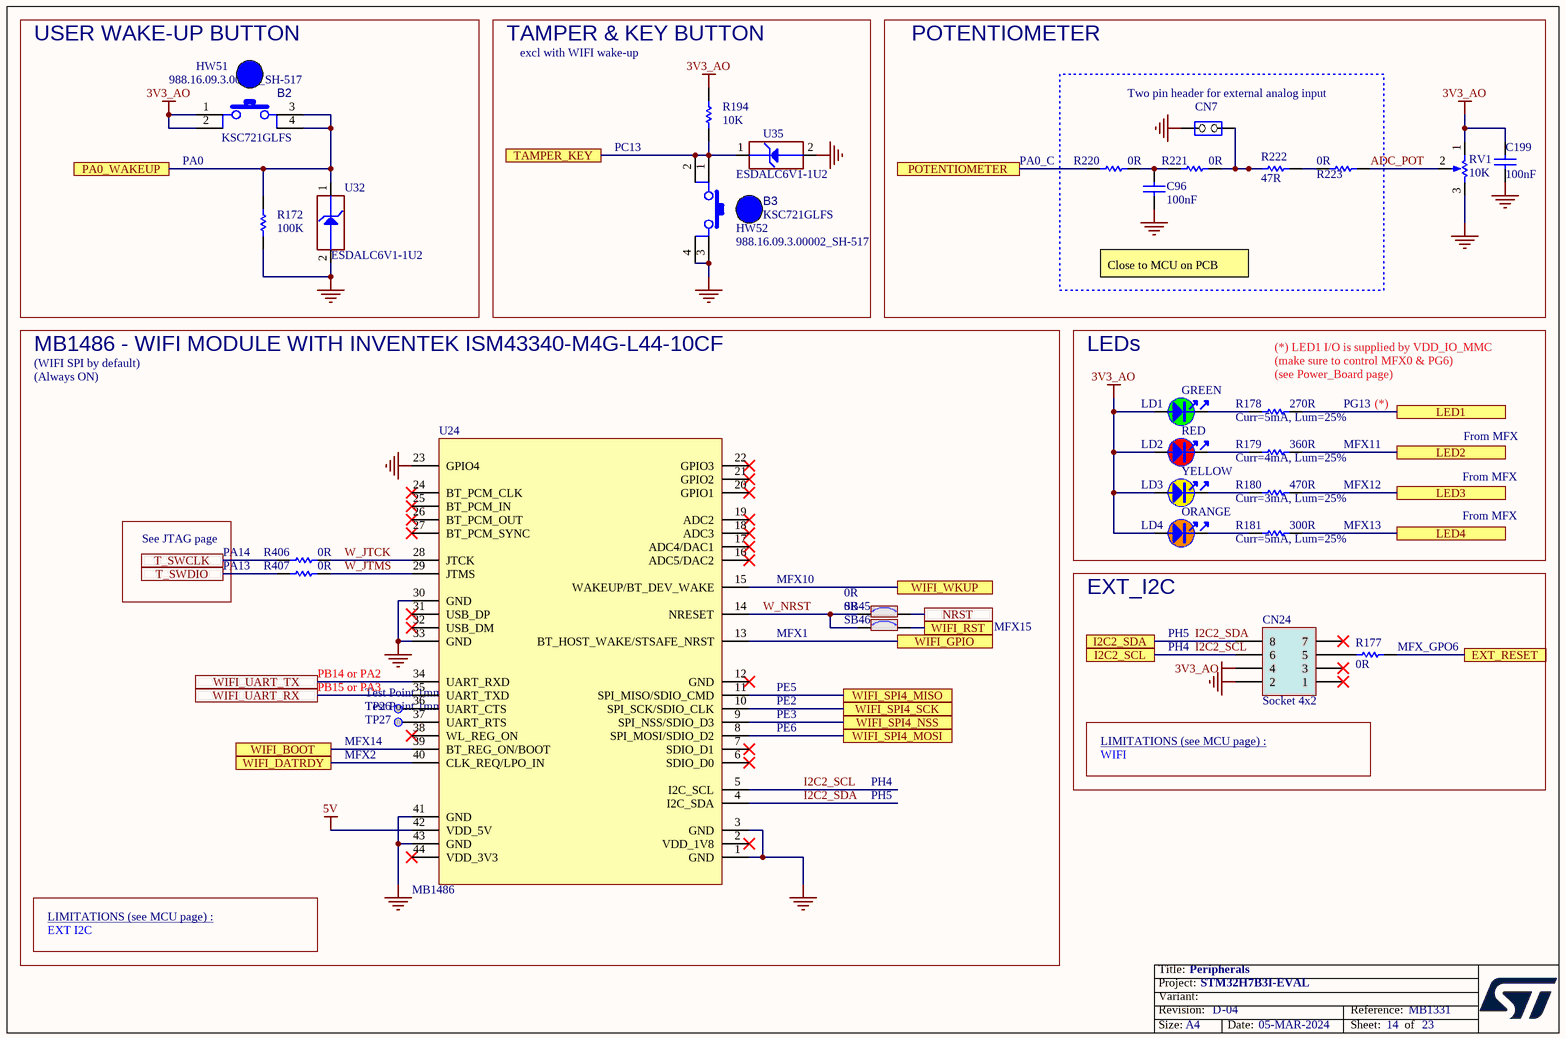
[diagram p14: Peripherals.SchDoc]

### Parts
B2  value KSC721GLFS  [SWI_C&K_KSC721GLFS_BLUE]  (hidden comment: SW_BLUE_KSC721GLFS)
B3  value KSC721GLFS  [SWI_C&K_KSC721GLFS_BLUE]  (hidden comment: SW_BLUE_KSC721GLFS)
C96  value 100nF  [C0603]  (hidden comment: Capacitor)
C199  value 100nF  [C0402]  (hidden comment: Capacitor)
CN7  Jumper_Header 2x1  [CON_SAMTEC_TSW-102-07-G-S]  (value not drawn)
CN24  Socket 4x2  [CON_SAMTEC_SSM-104-L-DH]
HW51  value 988.16.09.3.00002_SH-517  (hidden comment: BUTTON_HAT_BLUE)  (mechanical)
HW52  value 988.16.09.3.00002_SH-517  (hidden comment: BUTTON_HAT_BLUE)  (mechanical)
LD1  value GREEN  [LED_0603_OSRAM_LG-Q396-PS-35_GREEN_1A2K_H0P4]  (hidden comment: LED_green)
LD2  value RED  [LED_0603_VISHAY_VLMS1300-GS08_RED_1A2K_H0P8]  (hidden comment: LED_red)
LD3  value YELLOW  [LED_0603_OSRAM_LY-Q396-P1Q2-36_YELLOW_1A2K_H0P4]  (hidden comment: LED_yellow)
LD4  value ORANGE  [LED_0603_OSRAM_LO-Q976-PS-25_ORANGE_1A2K_H0P8]  (hidden comment: LED_orange)
R172  value 100K  [R0402]  (hidden comment: Resistor)
R177  value 0R  [R0402]  (hidden comment: Resistor)
R178  value 270R  [R0402]  (hidden comment: Resistor)
R179  value 360R  [R0402]  (hidden comment: Resistor)
R180  value 470R  [R0402]  (hidden comment: Resistor)
R181  value 300R  [R0402]  (hidden comment: Resistor)
R194  value 10K  [R0402]  (hidden comment: Resistor)
R220  value 0R  [R0603]  (hidden comment: Resistor)
R221  value 0R  [R0603]  (hidden comment: Resistor)
R222  value 47R  [R0603]  (hidden comment: Resistor)
R223  value 0R  [R0603]  (hidden comment: Resistor)
R406  value 0R  [R0402]  (hidden comment: Resistor)
R407  value 0R  [R0402]  (hidden comment: Resistor)
RV1  value 10K  [POT_BOURNS_3386P]  (hidden comment: POTENTIOMETER)
SB45  value 0R  [SOLDER-BRIDGE_R0603-0R]  (hidden comment: SB_ON)
SB46  value 0R  [SOLDER-BRIDGE_R0603-0R]  (hidden comment: SB_ON)
TP26  value Test Point 1mm  [TP_SMD_1MM]  (hidden comment: Test Point)  (no BOM)
TP27  value Test Point 1mm  [TP_SMD_1MM]  (hidden comment: Test Point)  (no BOM)
U24  value MB1486  [MOD_WIFI_INVENTEK_ISM43362]  (hidden comment: WIFI MODULE INTERPOSER)
U32  value ESDALC6V1-1U2  [ESD_ST0201]  (hidden comment: ESD-TRANSIL)
U35  value ESDALC6V1-1U2  [ESD_ST0201]  (hidden comment: ESD-TRANSIL)

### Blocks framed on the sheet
USER WAKE-UP BUTTON: B2 HW51 R172 U32
TAMPER & KEY BUTTON: B3 HW52 R194 U35
POTENTIOMETER: C199 RV1
Two pin header for external analog input: C96 CN7 R220-R223
MB1486 - WIFI MODULE WITH INVENTEK ISM43340-M4G-L44-10CF: R406 R407 SB45 SB46 TP26 TP27 U24
LEDs: LD1-LD4 R178-R181
EXT_I2C: CN24 R177

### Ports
EXT_RESET, I2C2_SCL, I2C2_SDA, LED1, LED2, LED3, LED4, NRST, PA0_WAKEUP, POTENTIOMETER, T_SWCLK, T_SWDIO, TAMPER_KEY, WIFI_BOOT, WIFI_DATRDY, WIFI_GPIO, WIFI_RST, WIFI_SPI4_MISO, WIFI_SPI4_MOSI, WIFI_SPI4_NSS, WIFI_SPI4_SCK, WIFI_UART_RX, WIFI_UART_TX, WIFI_WKUP

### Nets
3V3_AO: B2.1 B2.2 C199.1 CN24.4 LD1.1 LD2.1 LD3.1 LD4.1 R194.2 RV1.1(BOT)
5V: U24.42(VDD_5V)
GND: B3.3 B3.4 C96.2 C199.2 CN7.2(NO) CN24.2 R172.1 RV1.3(TOP) U24.1(GND) U24.3(GND) U24.23(GPIO4) U24.30(GND) U24.33(GND) U24.41(GND) U24.43(GND) U32.2(GND) U35.2(GND)
ADC_POT: R223.2 RV1.2(TAP)
EXT_RESET: R177.2 ; port EXT_RESET
I2C2_SCL: CN24.6 U24.5(I2C_SCL) ; port I2C2_SCL
I2C2_SDA: CN24.8 U24.4(I2C_SDA) ; port I2C2_SDA
JTAG_TCK: R406.1 ; port T_SWCLK
JTAG_TMS: R407.1 ; port T_SWDIO
LED2: R179.2 ; port LED2
LED3: R180.2 ; port LED3
LED4: R181.2 ; port LED4
NRST: SB45.2 ; port NRST
PA0_WAKEUP: B2.3 B2.4 R172.2 U32.1(IO1) ; port PA0_WAKEUP
PG13: R178.2 ; port LED1
POTENTIOMETER: R220.2 ; port POTENTIOMETER
TAMPER_KEY: B3.1 B3.2 R194.1 U35.1(IO1) ; port TAMPER_KEY
W_JTCK: R406.2 U24.28(JTCK)
W_JTMS: R407.2 U24.29(JTMS)
W_NRST: SB45.1 SB46.1 U24.14(NRESET)
WIFI_BOOT: U24.39(BT_REG_ON/BOOT) ; port WIFI_BOOT
WIFI_DATRDY: U24.40(CLK_REQ/LPO_IN) ; port WIFI_DATRDY
WIFI_GPIO: U24.13(BT_HOST_WAKE/STSAFE_NRST) ; port WIFI_GPIO
WIFI_RST: SB46.2 ; port WIFI_RST
WIFI_SPI4_MISO: U24.11(SPI_MISO/SDIO_CMD) ; port WIFI_SPI4_MISO
WIFI_SPI4_MOSI: U24.8(SPI_MOSI/SDIO_D2) ; port WIFI_SPI4_MOSI
WIFI_SPI4_NSS: U24.9(SPI_NSS/SDIO_D3) ; port WIFI_SPI4_NSS
WIFI_SPI4_SCK: U24.10(SPI_SCK/SDIO_CLK) ; port WIFI_SPI4_SCK
WIFI_UART_RX: U24.35(UART_TXD) ; port WIFI_UART_RX
WIFI_UART_TX: U24.34(UART_RXD) ; port WIFI_UART_TX
WIFI_WKUP: U24.15(WAKEUP/BT_DEV_WAKE) ; port WIFI_WKUP
NetC96_1: C96.1 R220.1 R221.1
NetCN7_1: CN7.1(COMMON) R221.2 R222.1
NetCN24_5: CN24.5 R177.1
NetLD1_2: LD1.2 R178.1
NetLD2_2: LD2.2 R179.1
NetLD3_2: LD3.2 R180.1
NetLD4_2: LD4.2 R181.1
NetR222_2: R222.2 R223.1
NetTP26_1: TP26.1 U24.36(UART_CTS)
NetTP27_1: TP27.1 U24.37(UART_RTS)

Not connected (* = marked no-connect by the designer): CN24 1* 3* 7*; U24 2(VDD_1V8)* 6(SDIO_D0)* 7(SDIO_D1)* 12(GND)* 16(ADC5/DAC2)* 17(ADC4/DAC1)* 18(ADC3)* 19(ADC2)* 20(GPIO1)* 21(GPIO2)* 22(GPIO3)* 24(BT_PCM_CLK)* 25(BT_PCM_IN)* 26(BT_PCM_OUT)* 27(BT_PCM_SYNC)* 31(USB_DP)* 32(USB_DM)* 38(WL_REG_ON)* 44(VDD_3V3)*

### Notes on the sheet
- excl with WIFI wake-up
- (near B2) PA0
- PC13
- (near R220) PA0_C
- Close to MCU on PCB
- (WIFI SPI by default)
- (Always ON)
- (near R178) (*) LED1 I/O is supplied by VDD_IO_MMC
  (make sure to control MFX0 & PG6)
  (see Power_Board page)
- (near R178) Curr=5mA, Lum=25%
- PG13
- MFX11
- (*)
- From MFX
- (near R179) Curr=4mA, Lum=25%
- (near R180) Curr=3mA, Lum=25%
- MFX12
- See JTAG page
- PA13
- PA14
- MFX10
- (near R181) Curr=5mA, Lum=25%
- MFX13
- MFX1
- MFX15
- PH5
- PH4
- (near R177) MFX_GPO6
- PB14 or PA2
- PB15 or PA3
- PE5
- PE3
- PE2
- MFX14
- MFX2
- PE6
- LIMITATIONS (see MCU page) :
- WIFI
- EXT I2C

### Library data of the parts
B2 B3 = MCD-00176: Switch HW BLUE High4.3mm 2.25 Newtons; Manufacturer: C&K; Part_Type: Misc; Part_Preference: Recommended; Provided_By: SUBCO; Component_Country_Of_Origin: France; ID: 2693; Order_Code_RS: 894-9152; ShowFields: YES
C96 = MCD-02119: Capacitor, MLCC, 100nF, 6V3, X5R, 10%, 0603, T=0,8mm; Manufacturer: KEMET; Manufacturer_Part_Number: C0603C104K9PACTU; Part_Preference: Recommended; ECCN_EU: NEC; ECCN_US: EAR99; Component_Country_Of_Origin: Mexico; ID: 4219; ShowFields: YES
C199 = MCD-00006: as C73 on sheet MFX
CN7 = MCD-00045: Header, 2x1, 2,54mm, VR, TH, Height 5.84mm/2.54mm; Manufacturer_Part_Number: TSW-102-07-G-S; Manufacturer: SAMTEC; Part_Type: Connector; Alternate_Manufacturer_Part_Number: 313102S111116;313102S111116; Alternate_Manufacturer: JIUBABA; LIANYI; Full_Alternate_Internal_Part_Number: MCD-02390; Part_Preference: Recommended; Partial_Alternate_Internal_Part_Number: MCD-02957, MCD-03720; Provided_By: SUBCO; Component_Country_Of_Origin: China, Costa Rica, Malaysia, USA, Vietnam; ID: 2545; Order_Code_RS: 2505044; ShowFields: YES
CN24 = MCD-00131: Socket, 4x2, 2.54mm, RA, SMT, Height 5.72mm; Manufacturer_Part_Number: SSM-104-L-DH; Manufacturer: SAMTEC; Part_Type: Connector; Alternate_Manufacturer_Part_Number: F206A-2x04MGF-LA; Alternate_Manufacturer: JIUBABA; Part_Preference: Recommended; Provided_By: SUBCO; ECCN_US: EAR99; ECCN_EU: NEC; Component_Country_Of_Origin: China, Costa Rica, Malaysia, USA, Vietnam; ID: 2740; Order_Code_RS: 198-1510; ShowFields: YES
HW51 HW52 = MCD-00634: Blue Hat for switch TD0341X-G01-BLU; Part_Type: Mechanical; Manufacturer: JIUBABA; Part_Preference: Alternate; Provided_By: SUBCO; Alternate_EMS: A; Component_Country_Of_Origin: Unknown; ID: 3112; ShowFields: YES
LD1 = MCD-00588: LED Green, 0603 SMD, Forward Voltage Typ=2V, Max=2.5V; Part_Type: Display; Manufacturer_Part_Number: LG Q396-PS-35; Manufacturer: OSRAM OPTO SEMICONDUCTORS; Alternate_Manufacturer_Part_Number: VLMTG1300-GS08; Alternate_Manufacturer: VISHAY SEMICONDUCTOR OPTO DIVISION; Part_Preference: Recommended; Partial_Alternate_Internal_Part_Number: MCD-02400, MCD-03155; Provided_By: SUBCO; Component_Country_Of_Origin: Unknown; ID: 3155; ShowFields: YES
LD2 = MCD-00587: LED Red, 0603 SMD, 2V Forward Voltage; Part_Type: Display; Manufacturer_Part_Number: VLMS1300-GS08; Manufacturer: VISHAY; Alternate_Manufacturer_Part_Number: LS Q976-NR-1; Alternate_Manufacturer: OSRAM OPTO SEMICONDUCTORS; Full_Alternate_Internal_Part_Number: MCD-02401; Part_Preference: Recommended; Provided_By: SUBCO; Component_Country_Of_Origin: China; ID: 3154; ShowFields: YES
LD3 = MCD-01061: LED Yellow, 0603 SMD, Forward Voltage min=1.7V, Typ=2V, Max=2.3V; Part_Type: Display; Manufacturer_Part_Number: LY Q396-P1Q2-36; Manufacturer: OSRAM OPTO SEMICONDUCTORS; Part_Preference: Recommended; Provided_By: SUBCO; Component_Country_Of_Origin: Unknown; ID: 3242; ShowFields: YES
LD4 = MCD-00590: LED Orange, 0603 SMD, Forward Voltage Min=1.6V, Max=2.4V; Part_Type: Display; Manufacturer_Part_Number: LO Q976-PS-25; Manufacturer: OSRAM OPTO SEMICONDUCTORS; Alternate_Manufacturer_Part_Number: VLMO1300-GS08; Alternate_Manufacturer: VISHAY SEMICONDUCTOR OPTO DIVISION; Part_Preference: Recommended; Provided_By: SUBCO; Component_Country_Of_Origin: Unknown; ID: 3156; ShowFields: YES
R172 = MCD-00059: Resistor,100K,0402,1%,1/16W; Manufacturer_Part_Number: RC0402FR-07100KL; Manufacturer: YAGEO; Alternate_Manufacturer_Part_Number: RT0402FRE07100KL; Part_Preference: Recommended; Partial_Alternate_Internal_Part_Number: MCD-03301; Provided_By: SUBCO; ECCN_US: EAR99; ECCN_EU: NEC; Component_Country_Of_Origin: China; ID: 2533; Order_Code_RS: 2421891; ShowFields: YES
R177 R406 R407 = MCD-00052: as R161 on sheet MFX
R178 = MCD-00441: Resistor,270R,0402,1%,1/16W; Manufacturer_Part_Number: RC0402FR-07270RL; Manufacturer: YAGEO; Part_Preference: Recommended; Provided_By: SUBCO; ECCN_US: EAR99; ECCN_EU: NEC; Component_Country_Of_Origin: China; ID: 2838; ShowFields: YES
R179 = MCD-00461: Resistor,360R,0402,1%,1/16W; Manufacturer_Part_Number: RC0402FR-07360RL; Manufacturer: YAGEO; Part_Preference: Recommended; Provided_By: SUBCO; ECCN_US: EAR99; ECCN_EU: NEC; Component_Country_Of_Origin: China; ID: 2816; ShowFields: YES
R180 = MCD-00178: Resistor,470R,0402,1%,1/16W; Manufacturer_Part_Number: RC0402FR-07470RL; Manufacturer: YAGEO; Part_Preference: Recommended; Provided_By: SUBCO; ECCN_US: EAR99; ECCN_EU: NEC; Component_Country_Of_Origin: China; ID: 2689; ShowFields: YES
R181 = MCD-00449: Resistor,300R,0402,1%,1/16W; Manufacturer_Part_Number: RC0402FR-07300RL; Manufacturer: YAGEO; Part_Preference: Recommended; Provided_By: SUBCO; ECCN_US: EAR99; ECCN_EU: NEC; Component_Country_Of_Origin: China; ID: 2832; ShowFields: YES
R194 = MCD-00053: as R166 on sheet MFX
R220 R221 R223 = MCD-00056: as R158 on sheet MFX
R222 = MCD-00482: Resistor,47R,0603,1%,1/10W; Manufacturer_Part_Number: RC0603FR-0747RL; Manufacturer: YAGEO; Part_Preference: Recommended; Provided_By: SUBCO; ECCN_US: EAR99; ECCN_EU: NEC; Component_Country_Of_Origin: China; ID: 2795; ShowFields: YES
RV1 = MCD-00575: TRIMMER 10K OHM 0.5W PC PIN; Part_Type: Resistor; Manufacturer_Part_Number: 3386P-1-103; Manufacturer: BOURNS; BMS_Part_Number: 9036661; Part_Preference: Recommended; Provided_By: SUBCO; ECCN_US: EAR99; ECCN_EU: NEC; Component_Country_Of_Origin: Costa Rica; ID: 3166; Order_Code_RS: 522-2693; ShowFields: YES
SB45 SB46 = MCD-00071: as SB2 on sheet MotorControl
TP26 TP27 = MCD-00074: as TP23 on sheet MFX
U24 = MCD-01999: 44 pins Interposer for WIFI module (MB1486 module is with INVENTEK ISM43340-M4G-L44-10CF); Part_Type: Misc; Manufacturer_Part_Number: MB1486 - WIFI MODULE WITH INVENTEK ISM43340-M4G-L44-10CF; Manufacturer: STMICROELECTRONICS; Manufacturer_HQ_COO: EU; Part_Preference: Recommended; ECCN_US: 5A002A4; Provided_By: SUBCO with ST control; Component_Country_Of_Origin: Unknown; ID: 4099; ShowFields: YES
U32 U35 = MCD-00170: ESD protection 6V1; Part_Type: Diode; Manufacturer: STMICROELECTRONICS; BMS_Part_Number: 9151132; Manufacturer_HQ_COO: EU; Part_Preference: Recommended; Provided_By: SUBCO with ST control; ECCN_US: EAR99; ECCN_EU: NEC; Component_Country_Of_Origin: China; ID: 2696; Order_Code_RS: 795-8404; ShowFields: YES

## Sheet Power_Board.SchDoc: Board Power
size A4; Date: Not used; ApprovedBy: Not used; CheckedBy: Not used; Author: Not used; CompanyName: STMicroelectronics; DrawnBy: Not used; Engineer: Not used; Organization: Not used; Address1: Not used; Address2: Not used; Address3: Not used; Address4: Not used; DocumentNumber: Not used; Revision: Not used; SheetNumber: 20; SheetTotal: 23
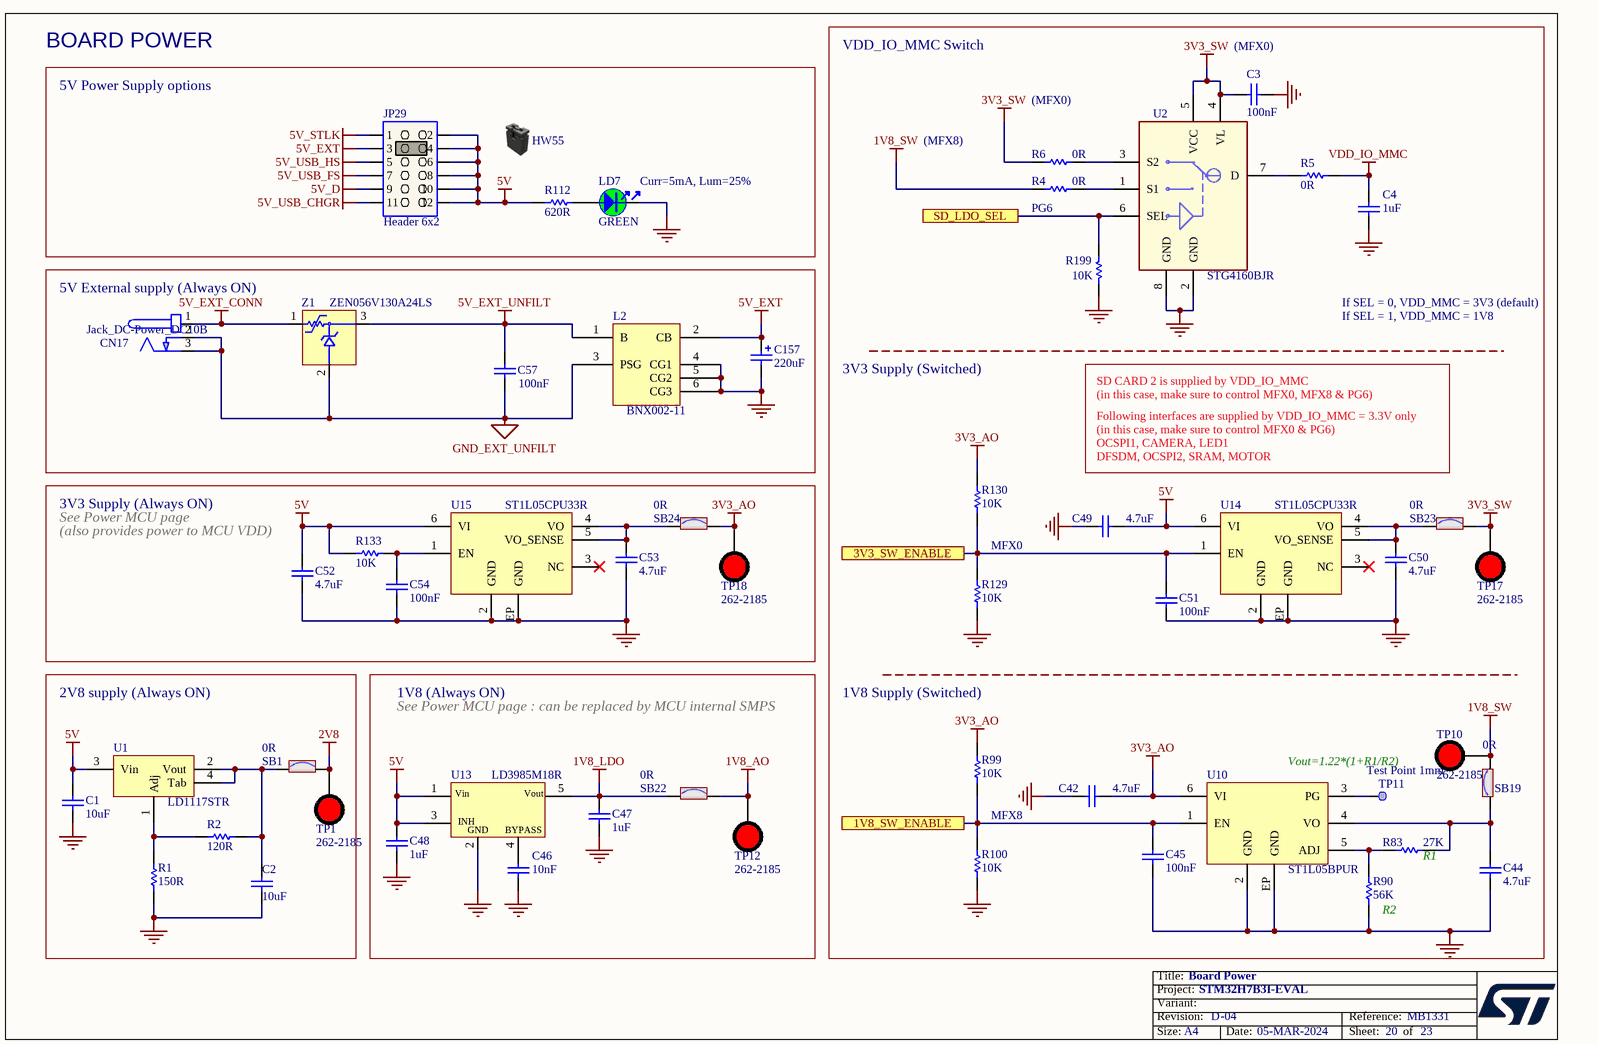
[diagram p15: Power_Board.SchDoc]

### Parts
C1  value 10uF  [C0603]  (hidden comment: Capacitor)
C2  value 10uF  [C0603]  (hidden comment: Capacitor)
C3  value 100nF  [C0402]  (hidden comment: Capacitor)
C4  value 1uF  [C0603]  (hidden comment: Capacitor)
C42  value 4.7uF  [C0603]  (hidden comment: Capacitor)
C44  value 4.7uF  [C0603]  (hidden comment: Capacitor)
C45  value 100nF  [C0402]  (hidden comment: Capacitor)
C46  value 10nF  [C0402]  (hidden comment: Capacitor)
C47  value 1uF  [C0402]  (hidden comment: Capacitor)
C48  value 1uF  [C0402]  (hidden comment: Capacitor)
C49  value 4.7uF  [C0603]  (hidden comment: Capacitor)
C50  value 4.7uF  [C0603]  (hidden comment: Capacitor)
C51  value 100nF  [C0402]  (hidden comment: Capacitor)
C52  value 4.7uF  [C0603]  (hidden comment: Capacitor)
C53  value 4.7uF  [C0603]  (hidden comment: Capacitor)
C54  value 100nF  [C0402]  (hidden comment: Capacitor)
C57  value 100nF  [C0402]  (hidden comment: Capacitor)
C157  value 220uF  [CPOL_TAJ-C_2312_H2P6]  (hidden comment: Cap_POL_TANA)
CN17  value Jack_DC-Power_DC10B  [CON_DC-POWER-SOCKET_CLIFF_FC68149_DC10B]  (hidden comment: Power_Jack_DC10B)
HW55  Shunt Black 2.54mm  (value not drawn)  (mechanical)
JP29  value Header 6x2  [CON_SAMTEC_TSW-106-07-X-D]  (hidden comment: Jumper_Header 6x2 Fitted 3-4)
L2  value BNX002-11  [FIL_MURATA_BNX002-01]  (hidden comment: BNX002-01)
LD7  value GREEN  [LED_0603_OSRAM_LG-Q396-PS-35_GREEN_1A2K_H0P4]  (hidden comment: LED_green)
R1  value 150R  [R0603]  (hidden comment: Resistor)
R2  value 120R  [R0603]  (hidden comment: Resistor)
R4  value 0R  [R0603]  (hidden comment: Resistor)
R5  value 0R  [R0603]  (hidden comment: Resistor)
R6  value 0R  [R0603]  (hidden comment: Resistor)
R83  value 27K  [R0402]  (hidden comment: Resistor)
R90  value 56K  [R0402]  (hidden comment: Resistor)
R99  value 10K  [R0402]  (hidden comment: Resistor)
R100  value 10K  [R0402]  (hidden comment: Resistor)
R112  value 620R  [R0402]  (hidden comment: Resistor)
R129  value 10K  [R0402]  (hidden comment: Resistor)
R130  value 10K  [R0402]  (hidden comment: Resistor)
R133  value 10K  [R0402]  (hidden comment: Resistor)
R199  value 10K  [R0402]  (hidden comment: Resistor)
SB1  value 0R  [SOLDER-BRIDGE_R0603-0R]  (hidden comment: SB_ON)
SB19  value 0R  [SOLDER-BRIDGE_R0603-0R]  (hidden comment: SB_ON)
SB22  value 0R  [SOLDER-BRIDGE_R0603-0R]  (hidden comment: SB_ON)
SB23  value 0R  [SOLDER-BRIDGE_R0603-0R]  (hidden comment: SB_ON)
SB24  value 0R  [SOLDER-BRIDGE_R0603-0R]  (hidden comment: SB_ON)
TP1  value 262-2185  [TP_PTH-1MM_TEST-TERMINAL_RS_262-2185_RED]  (hidden comment: Test_pin_conn_red)
TP10  value 262-2185  [TP_PTH-1MM_TEST-TERMINAL_RS_262-2185_RED]  (hidden comment: Test_pin_conn_red)
TP11  value Test Point 1mm  [TP_SMD_1MM]  (hidden comment: Test Point)  (no BOM)
TP12  value 262-2185  [TP_PTH-1MM_TEST-TERMINAL_RS_262-2185_RED]  (hidden comment: Test_pin_conn_red)
TP17  value 262-2185  [TP_PTH-1MM_TEST-TERMINAL_RS_262-2185_RED]  (hidden comment: Test_pin_conn_red)
TP18  value 262-2185  [TP_PTH-1MM_TEST-TERMINAL_RS_262-2185_RED]  (hidden comment: Test_pin_conn_red)
U1  LD1117STR  [REG_SOT223-TAB]
U2  value STG4160BJR  [ESD_FLIP-CHIP-BGA8_1P9X0P9_P050]  (hidden comment: STG4160)
U10  ST1L05BPUR  [ICC_DFN6-EPAD_3X3_P095]
U13  LD3985M18R  [REG_SOT23-5L]
U14  ST1L05CPU33R  [ICC_DFN6-EPAD_3X3_P095]
U15  ST1L05CPU33R  [ICC_DFN6-EPAD_3X3_P095]
Z1  ZEN056V130A24LS  [DIOZ_LITTELFUSE_ZEN056V130A24LS]

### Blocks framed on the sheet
BOARD POWER: HW55 JP29 LD7 R112
5V External supply (Always ON): C57 C157 CN17 L2 Z1
2V8 supply (Always ON): C1 C2 R1 R2 SB1 TP1 U1

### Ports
1V8_SW_ENABLE, 3V3_SW_ENABLE, SD_LDO_SEL

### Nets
1V8_AO: SB22.2 TP12.1
1V8_LDO: C47.2 SB22.1 U13.5(Vout)
1V8_SW: R4.1 SB19.2 TP10.1
2V8: SB1.2 TP1.1
3V3_AO: C42.1 R99.1 R130.1 SB24.2 TP18.1 U10.6(VI)
3V3_SW: C3.1 R6.1 SB23.2 TP17.1 U2.4(VL) U2.5(VCC)
5V: C1.2 C48.2 C49.1 C52.2 JP29.2 JP29.4 JP29.6 JP29.8 JP29.10 JP29.12 R112.1 R133.2 U1.3(Vin) U13.1(Vin) U13.3(CE) U14.6(VI) U15.6(VI)
5V_D: JP29.9
5V_EXT: C157.1 JP29.3 L2.2(CB)
5V_EXT_CONN: CN17.1 Z1.1
5V_EXT_UNFILT: C57.1 L2.1(B) Z1.3
5V_STLK: JP29.1
5V_USB_CHGR: JP29.11
5V_USB_FS: JP29.7
5V_USB_HS: JP29.5
GND: C1.1 C2.1 C3.2 C4.1 C42.2 C44.1 C45.2 C46.1 C47.1 C48.1 C49.2 C50.1 C51.2 C52.1 C53.1 C54.2 C157.2 L2.4(CG1) L2.5(CG2) L2.6(CG3) LD7.2 R1.1 R90.1 R100.2 R129.2 R199.1 U2.2(GND) U2.8(GND) U10.2(GND) U10.EP(GND) U13.2(GND) U14.2(GND) U14.EP(GND) U15.2(GND) U15.EP(GND)
GND_EXT_UNFILT: C57.2 CN17.2 CN17.3 L2.3(PSG) Z1.2
VDD_IO_MMC: C4.2 R5.2
1V8_SW_ENABLE: C45.1 R99.2 R100.1 U10.1(EN) ; port 1V8_SW_ENABLE
3V3_SW_ENABLE: C51.1 R129.1 R130.2 U14.1(EN) ; port 3V3_SW_ENABLE
SD_LDO_SEL: R199.2 U2.6(SEL) ; port SD_LDO_SEL
NetC2_2: C2.2 R2.1 SB1.1 U1.2(Vout) U1.4(Tab)
NetC44_2: C44.2 R83.1 SB19.1 U10.4(VO)
NetC46_2: C46.2 U13.4(BYPASS)
NetC50_2: C50.2 SB23.1 U14.4(VO) U14.5(VO_SENSE)
NetC53_2: C53.2 SB24.1 U15.4(VO) U15.5(VO_SENSE)
NetC54_1: C54.1 R133.1 U15.1(EN)
NetLD7_1: LD7.1 R112.2
NetR1_2: R1.2 R2.2 U1.1(Adj)
NetR4_2: R4.2 U2.1(S1)
NetR5_1: R5.1 U2.7(D)
NetR6_2: R6.2 U2.3(S2)
NetR83_2: R83.2 R90.2 U10.5(ADJ)
NetTP11_1: TP11.1 U10.3(PG)

Not connected (* = marked no-connect by the designer): U14 3(NC)*; U15 3(NC)*

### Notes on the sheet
- VDD_IO_MMC Switch
- (near C3) (MFX0)
- 5V Power Supply options
- (MFX0)
- (near LD7) Curr=5mA, Lum=25%
- (MFX8)
- (near R4) PG6
- If SEL = 0, VDD_MMC = 3V3 (default)
- If SEL = 1, VDD_MMC = 1V8
- 3V3 Supply (Switched)
- SD CARD 2 is supplied by VDD_IO_MMC
  (in this case, make sure to control MFX0, MFX8 & PG6)
- 3V3 Supply (Always ON)
- See Power MCU page
- Following interfaces are supplied by VDD_IO_MMC = 3.3V only
  (in this case, make sure to control MFX0 & PG6)
  OCSPI1, CAMERA, LED1
  DFSDM, OCSPI2, SRAM, MOTOR
- (near C52) (also provides power to MCU VDD)
- MFX0
- 1V8 (Always ON)
- See Power MCU page : can be replaced by MCU internal SMPS
- 1V8 Supply (Switched)
- Vout=1.22*(1+R1/R2)
- MFX8
- (near R83) R1
- (near R90) R2

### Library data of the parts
C1 C2 = MCD-00243: Capacitor, MLCC, 10uF, 6V3, X5R, 10%, 0603, T=0,8mm; Manufacturer_Part_Number: CC0603KRX5R5BB106; Manufacturer: YAGEO; Part_Preference: Recommended; Provided_By: SUBCO; ECCN_US: EAR99; ECCN_EU: NEC; Component_Country_Of_Origin: China; ID: 2626; ShowFields: YES
C3 C45 C51 C54 C57 = MCD-00006: as C73 on sheet MFX
C4 = MCD-00010: Capacitor, MLCC, 1uF, 16V, X5R, 10%, 0603, T=0,8mm; Manufacturer_Part_Number: CC0603KRX5R7BB105; Manufacturer: YAGEO; Part_Preference: Recommended; Provided_By: SUBCO; ECCN_US: EAR99; ECCN_EU: NEC; Component_Country_Of_Origin: China; ID: 2470; Order_Code_RS: 2370680; ShowFields: YES
C42 C44 C50 C53 = MCD-04044: Capacitor, MLCC, 4.7uF, 10V, X5R, 20%, 0603, T=0.8mm; Manufacturer_Part_Number: C0603C475M8PAC7040; Manufacturer: KEMET CORPORATION; Part_Preference: Recommended; Component_Country_Of_Origin: Mexico; ShowFields: YES; ID: 6160
C46 = MCD-00011: as C20 on sheet MotorControl
C47 C48 = MCD-00095: Capacitor, MLCC, 1uF, 6V3, X5R, 10%, 0402, T=0,5mm; Manufacturer_Part_Number: GRM155R61E105KA12; Manufacturer: MURATA; Alternate_Manufacturer_Part_Number: GRM155R60J105KE19; Part_Preference: Recommended; Provided_By: SUBCO; ECCN_US: EAR99; ECCN_EU: NEC; Component_Country_Of_Origin: Japan°°; ID: 2772; Order_Code_RS: 2218855; ShowFields: YES
C49 C52 = MCD-00097: Capacitor, MLCC, 4.7uF, 16V, X5R, 20%, 0603, T=0,8mm; Manufacturer_Part_Number: GRM188R61C475KE11; Manufacturer: MURATA; Alternate_Manufacturer_Part_Number: GRM188R61C475MAAJ; Part_Preference: Recommended; Provided_By: SUBCO; ECCN_US: EAR99; ECCN_EU: NEC; Component_Country_Of_Origin: Japan°°; ID: 2767; ShowFields: YES
C157 = MCD-00142: Capacitor, Tantalum, 220uF, 10V, 10%, 500mOhms, pkg Type_C (6032 metric), T=2.6mm; Manufacturer_Part_Number: TAJC227K010R; Manufacturer: AVX; Part_Preference: Recommended; Provided_By: SUBCO; ECCN_US: EAR99; ECCN_EU: NEC; Component_Country_Of_Origin: El Salvador; ID: 2730; Order_Code_RS: 136-4443; ShowFields: YES
CN17 = MCD-00173: DC-Power-Jack, 2.5mm, 5A, RA, TH; Manufacturer_Part_Number: DC10B; Manufacturer: CLIFF; Part_Type: Connector; BMS_Part_Number: 9087803; Part_Preference: Recommended; Provided_By: SUBCO; Component_Country_Of_Origin: Taiwan; ID: 2695; ShowFields: YES
HW55 = MCD-00043: SHUNT 2.54mm BLACK; Part_Type: Misc; Manufacturer: SAMTEC; Alternate_Manufacturer_Part_Number: 316102S111A; Alternate_Manufacturer: JIUBABA; Full_Alternate_Internal_Part_Number: MCD-02388; Manufacturer_HQ_COO: Unknown; Part_Preference: Recommended; Partial_Alternate_Internal_Part_Number: MCD-01849; Value: SNT-100-BK-G; Provided_By: SUBCO; Alternate_EMS: A; Component_Country_Of_Origin: China, Costa Rica, Malaysia, USA, Vietnam; ID: 2551; Order_Code_RS: 158-7784; ShowFields: YES
JP29 = MCD-01147: Header, 6x2, 2,54mm, VR, TH, Height 5.84mm/2.54mm - Shunt Fitted 1-2; Part_Type: Connector; Manufacturer_Part_Number: TSW-106-07-G-D; Manufacturer: SAMTEC; Part_Preference: Recommended; Provided_By: SUBCO; Component_Country_Of_Origin: China, Costa Rica, Malaysia, USA, Vietnam; ID: 3351; Order_Code_RS: 161-2280; ShowFields: YES
L2 = MCD-02155: Inductor, DC power EMI line filter, 40dB min (1MHz - 1GHz) insertion loss; Manufacturer: MURATA; Part_Preference: Recommended; Provided_By: SUBCO; Component_Country_Of_Origin: Unknown; ID: 4255; ShowFields: YES
LD7 = MCD-00588: as LD1 on sheet Peripherals
R1 = MCD-00394: Resistor,150,0603,1%,1/10W; Manufacturer_Part_Number: RC0603FR-07150RL; Manufacturer: YAGEO; Part_Preference: Recommended; Provided_By: SUBCO; ECCN_US: EAR99; ECCN_EU: NEC; Component_Country_Of_Origin: China; ID: 2879; ShowFields: YES
R2 = MCD-00338: Resistor,120R,0603,1%,1/10W; Manufacturer_Part_Number: RC0603FR-07120RL; Manufacturer: YAGEO; BMS_Part_Number: 9129734; Part_Preference: Recommended; Provided_By: SUBCO; ECCN_US: EAR99; ECCN_EU: NEC; Component_Country_Of_Origin: China; ID: 2939; ShowFields: YES
R4-R6 = MCD-00056: as R158 on sheet MFX
R83 = MCD-00443: Resistor,27K,0402,1%,1/16W; Manufacturer_Part_Number: RC0402FR-0727KL; Manufacturer: YAGEO; Part_Preference: Recommended; Provided_By: SUBCO; ECCN_US: EAR99; ECCN_EU: NEC; Component_Country_Of_Origin: China; ID: 2834; ShowFields: YES
R90 = MCD-00493: Resistor,56K,0402,1%,1/16W; Manufacturer_Part_Number: RC0402FR-0756KL; Manufacturer: YAGEO; Part_Preference: Recommended; Provided_By: SUBCO; ECCN_US: EAR99; ECCN_EU: NEC; Component_Country_Of_Origin: China; ID: 2784; ShowFields: YES
R99 R100 R129 R130 R133 R199 = MCD-00053: as R166 on sheet MFX
R112 = MCD-00499: Resistor,620R,0402,1%,1/16W; Manufacturer_Part_Number: RC0402FR-07620RL; Manufacturer: YAGEO; Part_Preference: Recommended; Provided_By: SUBCO; ECCN_US: EAR99; ECCN_EU: NEC; Component_Country_Of_Origin: China; ID: 2781; ShowFields: YES
SB1 SB19 SB22-SB24 = MCD-00071: as SB2 on sheet MotorControl
TP1 TP10 TP12 TP17 TP18 = MCD-00712: RS Pro 1mm Red Test Terminal; Part_Type: Misc; Manufacturer: RS PRO; Part_Preference: Recommended; Provided_By: SUBCO; Component_Country_Of_Origin: UK; ID: 3035; ShowFields: YES
TP11 = MCD-00074: as TP23 on sheet MFX
U1 = MCD-00721: LDO Voltage Regulator, Adjustable, 15V in, 1.1V drop, 1.25V to 15V/0.8A out, SOT-223-3; Part_Type: IC; Manufacturer: STMICROELECTRONICS; BMS_Part_Number: 9176132; Manufacturer_HQ_COO: EU; Part_Preference: Recommended; Partial_Alternate_Internal_Part_Number: MCD-02765; Provided_By: SUBCO with ST control; ECCN_US: EAR99; ECCN_EU: NEC; Component_Country_Of_Origin: China; ID: 3025; Order_Code_RS: 686-9363; ShowFields: YES
U2 = MCD-00668: Low voltage 0.5 ohm single SPDT switch with break-before-make feature and 15 kV contact ESD protection; Manufacturer: STMICROELECTRONICS; Part_Type: IC; BMS_Part_Number: 9180003; Manufacturer_HQ_COO: EU; Part_Preference: Forbidden; Provided_By: SUBCO with ST control; ECCN_US: EAR99; ECCN_EU: NEC; Component_Country_Of_Origin: Italy; ID: 3074; ShowFields: YES
U10 = MCD-00581: LDO Linear Voltage Regulator IC Positive Adjustable 1 Output Adjustable 1.3A 6-DFN (3x3); Manufacturer: STMICROELECTRONICS; BMS_Part_Number: 9176239; Manufacturer_HQ_COO: EU; Part_Preference: Recommended; Provided_By: SUBCO with ST control; ECCN_US: EAR99; ECCN_EU: NEC; Component_Country_Of_Origin: Malaysia; ID: 3163; Order_Code_RS: 188-9209; ShowFields: YES
U13 = MCD-00078: Ultra low drop-low noise BiCMOS voltage, regulators low ESR capacitors compatible; Manufacturer: STMICROELECTRONICS; Part_Type: IC; BMS_Part_Number: 9176159; Manufacturer_HQ_COO: EU; Part_Preference: Recommended; Provided_By: SUBCO with ST control; ECCN_US: EAR99; ECCN_EU: NEC; Component_Country_Of_Origin: Malaysia; ID: 2516; Order_Code_RS: 686-8830; ShowFields: YES
U14 U15 = MCD-01025: LDO, 3.3V, 1.3A, Very low quiescent current BiCMOS voltage regulator; Part_Type: IC; Manufacturer: STMICROELECTRONICS; BMS_Part_Number: 9176246; Manufacturer_HQ_COO: EU; Part_Preference: Recommended; Provided_By: SUBCO with ST control; ECCN_US: EAR99; ECCN_EU: NEC; Component_Country_Of_Origin: Malaysia; ID: 2998; ShowFields: YES
Z1 = MCD-00149: Protection circuit Zener Diode; Manufacturer: LITTELFUSE; BMS_Part_Number: 9127091; Part_Preference: Forbidden; Provided_By: SUBCO; ECCN_US: EAR99; ECCN_EU: NEC; ID: 2716; Order_Code_RS: 494-723; ShowFields: YES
